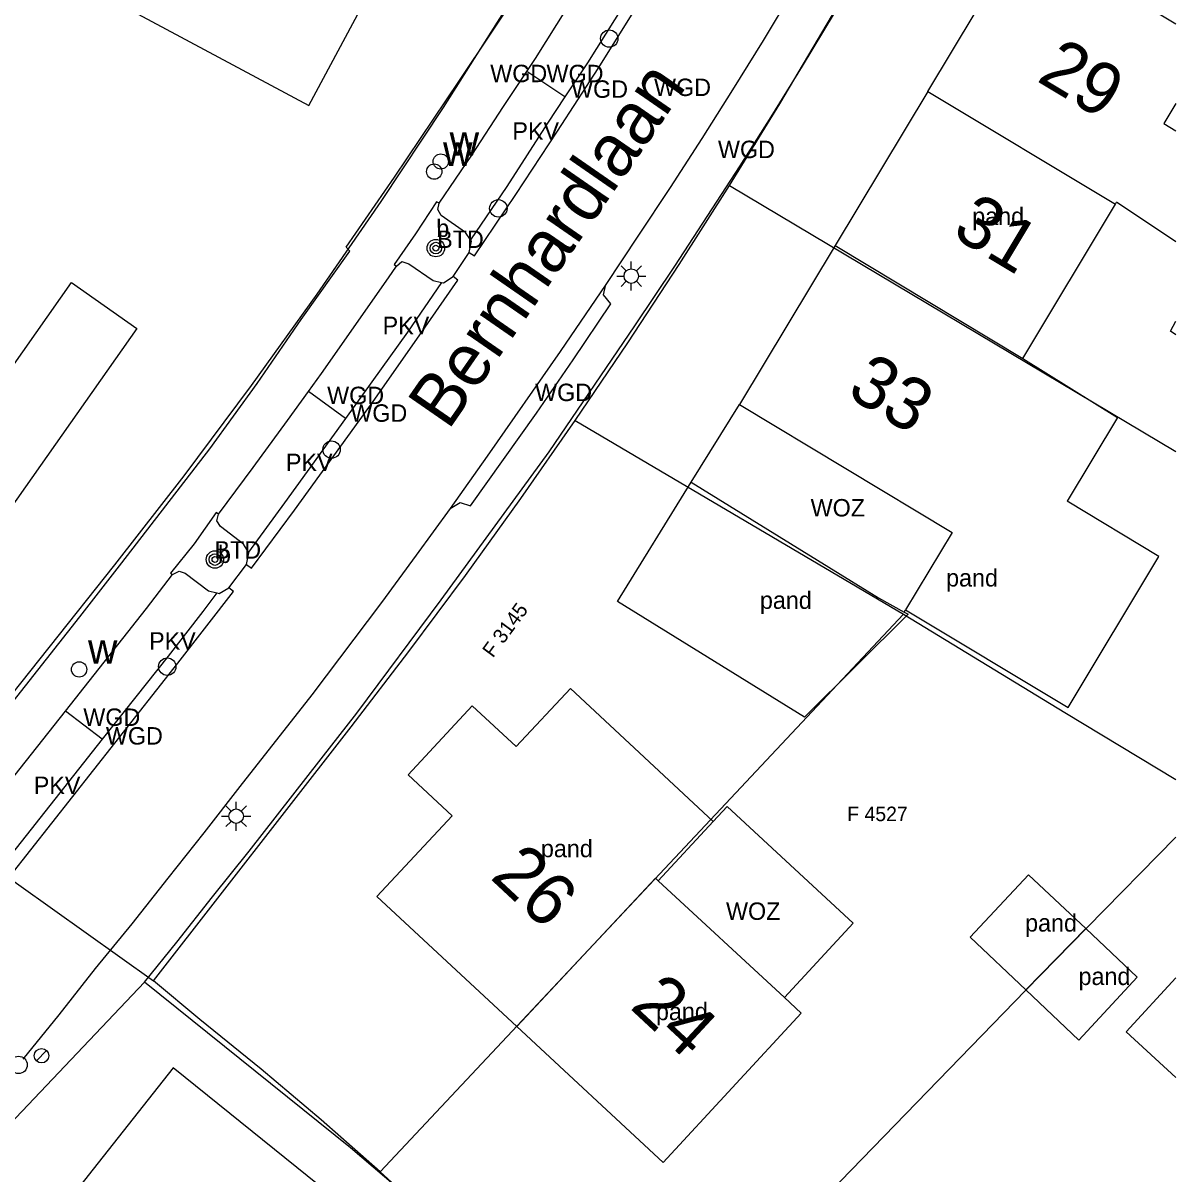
# Model space of a CAD drawing. Extents: x 198240 to 198429, y 356553 to 356721.
# Drawn here: x 198389.56 to 198429.25, y 356639.08 to 356678.7 of the extents above; entities that cross this region are included whole.
import ezdxf

# ---------------------------------------------------------------- set-up
doc = ezdxf.new("R2010")
doc.units = 0
for name, color, linetype in [('Afsluitpaal', 7, 'Continuous'), ('begroeid terreindeel kenmerkpunt', 7, 'Continuous'), ('bijgebouw', 7, 'Continuous'), ('BOOM', 7, 'Continuous'), ('grens individueel parkeervak', 7, 'Continuous'), ('Grens maaiveld', 7, 'Continuous'), ('grens WOZ object', 7, 'Continuous'), ('hoofdgebouw', 7, 'Continuous'), ('huisnummerreeks BGT', 7, 'Continuous'), ('identificerend kenmerkpunt bijpand', 7, 'Continuous'), ('identificerend kenmerkpunt pand', 7, 'Continuous'), ('identificerend kenmerkpunt parkeervak', 7, 'Continuous'), ('identificerend kenmerkpunt WOZ object', 7, 'Continuous'), ('kant verharding', 7, 'Continuous'), ('kolk', 7, 'Continuous'), ('LICHTMAST', 7, 'Continuous'), ('openbare ruimte label tekst', 7, 'Continuous'), ('Perceelnummer', 7, 'Continuous'), ('perceelsgrens_definitief', 7, 'Continuous'), ('tussenmuur', 7, 'Continuous'), ('tussenmuur bijgebouw (GBKN Zuid)', 7, 'Continuous'), ('vlakafsluiter', 7, 'Continuous'), ('waterleidingput', 7, 'Continuous'), ('wegdeel kenmerkpunt', 7, 'Continuous'), ('weginrichtingselement', 7, 'Continuous'), ('weginrichtingselement lijn', 7, 'Continuous')]:
    doc.layers.add(name, color=color, linetype=linetype)

msp = doc.modelspace()

# ---------------------------------------------------------------- linework, layer by layer
at = {"layer": 'Afsluitpaal'}
msp.add_line((198390.367, 356643.327), (198390.017, 356642.97), dxfattribs=at)
msp.add_circle((198390.194, 356643.147), 0.25, dxfattribs=at)
at = {"layer": 'bijgebouw'}
for p, q in [((198412.563, 356662.894), (198419.007, 356658.91)), ((198419.007, 356658.91), (198419.893, 356658.421))]:
    msp.add_line(p, q, dxfattribs=at)
for points in [[(198429.251, 356667.971), (198429.059, 356668.094), (198429.251, 356668.439)], [(198416.467, 356654.801), (198410.023, 356658.785), (198412.563, 356662.894)], [(198419.893, 356658.421), (198420.032, 356658.344), (198416.467, 356654.801)], [(198424.085, 356645.412), (198422.17, 356647.232), (198424.18, 356649.372), (198426.147, 356647.521)], [(198424.085, 356645.412), (198425.907, 356643.68), (198427.917, 356645.855), (198426.147, 356647.521)], [(198429.251, 356642.4), (198427.543, 356643.969), (198429.251, 356645.827)]]:
    msp.add_lwpolyline(points, dxfattribs=at)
at = {"layer": 'BOOM'}
for centre, radius in [((198403.77, 356670.952), 0.3), ((198403.77, 356670.952), 0.2), ((198403.77, 356670.952), 0.1), ((198396.164, 356660.23), 0.3), ((198396.164, 356660.23), 0.2), ((198396.164, 356660.23), 0.1)]:
    msp.add_circle(centre, radius, dxfattribs=at)
at = {"layer": 'grens individueel parkeervak'}
for p, q in [((198408.215, 356676.157), (198406.901, 356677.03)), ((198400.66, 356665.089), (198399.384, 356666.017)), ((198392.286, 356654.04), (198391.017, 356655.011))]:
    msp.add_line(p, q, dxfattribs=at)
at = {"layer": 'Grens maaiveld'}
for points in [[(198404.916, 356670.796), (198405.102, 356670.682), (198406.526, 356672.803), (198407.964, 356674.984), (198409.355, 356677.141), (198410.82, 356679.462), (198412.025, 356681.421), (198411.835, 356681.521)], [(198397.249, 356660.06), (198397.419, 356659.931), (198398.904, 356661.934), (198401.607, 356665.673), (198403.112, 356667.812), (198404.529, 356669.851), (198404.366, 356669.975)], [(198388.2, 356648.534), (198388.372, 356648.404), (198394.89, 356656.659), (198396.809, 356659.133), (198396.637, 356659.256)]]:
    msp.add_lwpolyline(points, dxfattribs=at)
at = {"layer": 'grens WOZ object'}
for p, q in [((198412.563, 356662.894), (198414.222, 356665.562)), ((198419.893, 356658.421), (198419.94, 356658.497)), ((198415.769, 356645.151), (198418.134, 356647.705))]:
    msp.add_line(p, q, dxfattribs=at)
msp.add_lwpolyline([(198413.323, 356651.216), (198413.795, 356651.724), (198418.134, 356647.705)], dxfattribs=at)
at = {"layer": 'hoofdgebouw'}
for p, q in [((198420.705, 356676.348), (198417.515, 356671.041)), ((198429.251, 356675.927), (198428.836, 356675.237)), ((198423.978, 356667.156), (198427.169, 356672.463)), ((198427.169, 356672.463), (198427.209, 356672.53)), ((198429.251, 356671.164), (198427.209, 356672.53)), ((198417.515, 356671.041), (198414.222, 356665.562)), ((198413.323, 356651.216), (198411.425, 356649.173)), ((198415.769, 356645.151), (198411.425, 356649.173))]:
    msp.add_line(p, q, dxfattribs=at)
for points in [[(198395.77, 356685.089), (198394.02, 356681.827), (198390.856, 356683.525), (198389.57, 356681.128), (198399.396, 356675.858), (198402.431, 356681.517)], [(198420.705, 356676.348), (198423.998, 356681.827), (198429.251, 356678.669)], [(198428.836, 356675.237), (198429.251, 356674.985)], [(198387.606, 356667.94), (198389.176, 356666.838), (198391.229, 356669.763), (198393.474, 356668.18), (198387.045, 356659.064), (198381.8, 356662.748)], [(198423.978, 356667.156), (198427.239, 356665.121), (198425.505, 356662.235)], [(198414.222, 356665.562), (198421.542, 356661.163), (198419.94, 356658.497)], [(198419.94, 356658.497), (198425.537, 356655.134), (198428.663, 356660.337), (198425.505, 356662.235)], [(198406.554, 356644.154), (198401.737, 356648.628), (198404.327, 356651.409), (198402.814, 356652.814), (198405.026, 356655.195), (198406.541, 356653.787), (198408.408, 356655.792), (198413.323, 356651.216)], [(198406.554, 356644.154), (198411.595, 356639.471), (198416.353, 356644.61), (198415.769, 356645.151)]]:
    msp.add_lwpolyline(points, dxfattribs=at)
at = {"layer": 'kant verharding'}
for p, q in [((198404.366, 356669.975), (198404.916, 356670.796)), ((198396.637, 356659.256), (198397.249, 356660.06)), ((198387.265, 356650.262), (198391.017, 356655.011)), ((198392.286, 356654.04), (198388.264, 356648.959))]:
    msp.add_line(p, q, dxfattribs=at)
for points in [[(198393.74, 356645.683), (198394.852, 356647.053), (198396.077, 356648.617), (198397.345, 356650.191), (198399.817, 356653.369), (198401.05, 356654.94), (198403.957, 356658.838), (198407.667, 356663.939), (198410.624, 356668.271), (198412.002, 356670.335), (198414.253, 356673.784), (198415.317, 356675.477), (198416.394, 356677.211), (198417.49, 356679.043), (198418.49, 356680.762), (198419.487, 356682.592), (198420.694, 356684.729), (198420.885, 356685.099)], [(198418.513, 356684.184), (198418.032, 356683.303), (198416.065, 356679.815), (198415.042, 356678.098), (198413.982, 356676.397), (198412.924, 356674.725), (198411.836, 356673.035), (198410.73, 356671.365), (198409.617, 356669.703)], [(198406.901, 356677.03), (198407.203, 356677.485), (198409.346, 356680.906), (198409.862, 356681.744)], [(198411.465, 356681.29), (198408.989, 356677.334), (198408.215, 356676.157)], [(198386.018, 356651.295), (198391.518, 356658.255), (198392.958, 356660.111), (198395.988, 356664.044), (198397.623, 356666.296), (198399.129, 356668.492), (198400.809, 356670.844), (198400.678, 356670.983), (198402.35, 356673.392), (198404.586, 356676.725), (198406.76, 356679.993)], [(198403.882, 356672.494), (198405.006, 356674.154), (198406.103, 356675.828), (198406.901, 356677.03)], [(198408.215, 356676.157), (198407.619, 356675.251), (198406.216, 356673.069), (198404.965, 356671.24)], [(198403.882, 356672.494), (198403.798, 356672.543), (198403.071, 356671.442), (198402.34, 356670.387), (198402.414, 356670.335)], [(198404.965, 356671.24), (198404.791, 356671.493), (198403.95, 356672.078), (198403.835, 356672.281), (198403.882, 356672.494)], [(198404.916, 356670.796), (198405.002, 356671.186), (198404.965, 356671.24)], [(198399.384, 356666.017), (198399.83, 356666.637), (198402.139, 356669.925), (198402.414, 356670.335)], [(198402.414, 356670.335), (198402.599, 356670.495), (198402.844, 356670.406), (198403.677, 356669.833), (198403.966, 356669.771)], [(198403.966, 356669.771), (198404.034, 356669.756), (198404.366, 356669.975)], [(198403.966, 356669.771), (198402.79, 356668.058), (198400.66, 356665.089)], [(198404.26, 356661.992), (198404.61, 356662.199), (198404.961, 356662.082), (198407.233, 356665.273), (198408.493, 356667.107), (198409.79, 356669.031), (198409.542, 356669.344), (198409.617, 356669.703)], [(198409.617, 356669.703), (198408.045, 356667.387), (198405.534, 356663.79), (198404.26, 356661.992)], [(198396.284, 356661.79), (198397.477, 356663.397), (198398.66, 356665.012), (198399.384, 356666.017)], [(198400.66, 356665.089), (198398.561, 356662.182), (198397.323, 356660.483)], [(198404.26, 356661.992), (198403.096, 356660.379), (198401.903, 356658.745), (198399.503, 356655.567), (198397.022, 356652.414), (198395.783, 356650.82), (198394.543, 356649.264), (198393.305, 356647.686), (198392.04, 356646.144), (198390.785, 356644.559), (198389.546, 356643.023)], [(198396.284, 356661.79), (198396.204, 356661.844), (198395.447, 356660.766), (198394.63, 356659.765), (198394.707, 356659.713)], [(198397.323, 356660.483), (198397.153, 356660.763), (198396.354, 356661.369), (198396.231, 356661.567), (198396.284, 356661.79)], [(198397.249, 356660.06), (198397.336, 356660.462), (198397.323, 356660.483)], [(198391.017, 356655.011), (198393.805, 356658.546), (198394.707, 356659.713)], [(198394.707, 356659.713), (198394.929, 356659.831), (198395.139, 356659.76), (198395.944, 356659.152), (198396.228, 356659.082)], [(198396.228, 356659.082), (198396.307, 356659.063), (198396.637, 356659.256)], [(198396.228, 356659.082), (198395.752, 356658.445), (198394.551, 356656.901), (198392.286, 356654.04)], [(198429.251, 356611.63), (198423.819, 356617.345), (198409.544, 356631.708), (198408.091, 356633.148), (198406.605, 356634.587), (198405.359, 356635.839), (198403.884, 356637.248), (198402.388, 356638.638), (198400.833, 356639.97), (198393.74, 356645.683)], [(198405.457, 356633.424), (198404.207, 356634.656), (198402.756, 356636.046), (198401.298, 356637.391), (198399.756, 356638.679), (198394.727, 356642.73), (198388.921, 356635.368)]]:
    msp.add_lwpolyline(points, dxfattribs=at)
at = {"layer": 'kolk'}
for centre in [(198409.74, 356678.166), (198405.923, 356672.32), (198400.179, 356664.016), (198394.523, 356656.542), (198389.403, 356642.831)]:
    msp.add_circle(centre, 0.3, dxfattribs=at)
at = {"layer": 'LICHTMAST'}
for p, q in [((198410.322, 356670.166), (198410.145, 356670.343)), ((198410.499, 356670.239), (198410.499, 356670.489)), ((198410.676, 356670.166), (198410.853, 356670.343)), ((198409.999, 356669.989), (198410.249, 356669.989)), ((198410.749, 356669.989), (198410.999, 356669.989)), ((198410.145, 356669.635), (198410.322, 356669.812)), ((198410.499, 356669.489), (198410.499, 356669.739)), ((198410.853, 356669.635), (198410.676, 356669.812)), ((198396.718, 356651.57), (198396.541, 356651.747)), ((198396.895, 356651.643), (198396.895, 356651.893)), ((198397.072, 356651.57), (198397.249, 356651.747)), ((198396.395, 356651.393), (198396.645, 356651.393)), ((198397.145, 356651.393), (198397.395, 356651.393)), ((198396.541, 356651.039), (198396.718, 356651.216)), ((198396.895, 356650.893), (198396.895, 356651.143)), ((198397.249, 356651.039), (198397.072, 356651.216))]:
    msp.add_line(p, q, dxfattribs=at)
for centre in [(198410.499, 356669.989), (198396.895, 356651.393)]:
    msp.add_circle(centre, 0.25, dxfattribs=at)
at = {"layer": 'perceelsgrens_definitief'}
for points in [[(198392.722, 356660.05), (198395.103, 356663.112), (198397.425, 356666.219), (198399.689, 356669.369), (198401.891, 356672.562), (198404.033, 356675.796), (198406.114, 356679.07), (198408.131, 356682.383), (198410.086, 356685.733), (198411.977, 356689.12), (198413.803, 356692.543), (198415.563, 356695.999), (198417.258, 356699.488), (198418.887, 356703.008), (198420.448, 356706.559), (198421.942, 356710.139)], [(198415.612, 356675.921), (198417.581, 356679.235), (198419.491, 356682.582), (198420.752, 356684.884)], [(198413.879, 356673.105), (198415.612, 356675.921)], [(198408.569, 356665.016), (198410.378, 356667.687), (198412.148, 356670.383), (198413.879, 356673.105)], [(198413.879, 356673.105), (198429.251, 356663.954)], [(198400.851, 356654.466), (198402.838, 356657.061), (198404.787, 356659.684), (198406.698, 356662.336), (198408.569, 356665.016)], [(198408.569, 356665.016), (198419.867, 356658.348)], [(198385.92, 356651.508), (198392.722, 356660.05)], [(198401.857, 356639.146), (198419.867, 356658.348)], [(198419.867, 356658.348), (198425.422, 356654.961), (198429.251, 356652.654)], [(198394.046, 356645.723), (198400.851, 356654.466)], [(198385.92, 356651.508), (198394.046, 356645.723)], [(198426.178, 356647.553), (198429.251, 356650.666)], [(198424.066, 356645.393), (198426.178, 356647.553)], [(198395.648, 356644.396), (198394.046, 356645.723)], [(198410.2, 356631.088), (198424.066, 356645.393)], [(198401.857, 356639.146), (198399.822, 356640.937), (198397.752, 356642.687), (198395.648, 356644.396)], [(198408.397, 356632.877), (198406.267, 356635.018), (198404.086, 356637.108), (198401.857, 356639.146)]]:
    msp.add_lwpolyline(points, dxfattribs=at)
at = {"layer": 'tussenmuur'}
for p, q in [((198420.705, 356676.348), (198427.169, 356672.463)), ((198417.515, 356671.041), (198423.978, 356667.156))]:
    msp.add_line(p, q, dxfattribs=at)
msp.add_lwpolyline([(198406.554, 356644.154), (198411.337, 356649.254), (198411.425, 356649.173)], dxfattribs=at)
at = {"layer": 'tussenmuur bijgebouw (GBKN Zuid)'}
msp.add_line((198424.085, 356645.412), (198426.147, 356647.521), dxfattribs=at)
at = {"layer": 'vlakafsluiter'}
msp.add_line((198387.884, 356639.508), (198393.74, 356645.683), dxfattribs=at)
at = {"layer": 'waterleidingput'}
for centre in [(198403.94, 356673.934), (198403.94, 356673.934), (198403.714, 356673.585), (198403.714, 356673.585), (198391.489, 356656.448), (198391.489, 356656.448)]:
    msp.add_circle(centre, 0.263, dxfattribs=at)
at = {"layer": 'weginrichtingselement lijn'}
for points in [[(198404.916, 356670.796), (198405.102, 356670.682), (198406.526, 356672.803), (198407.964, 356674.984), (198409.355, 356677.141), (198410.82, 356679.462), (198412.025, 356681.421), (198411.835, 356681.521)], [(198397.249, 356660.06), (198397.419, 356659.931), (198398.904, 356661.934), (198401.607, 356665.673), (198403.112, 356667.812), (198404.529, 356669.851), (198404.366, 356669.975)], [(198388.2, 356648.534), (198388.372, 356648.404), (198394.89, 356656.659), (198396.809, 356659.133), (198396.637, 356659.256)]]:
    msp.add_lwpolyline(points, dxfattribs=at)

# ---------------------------------------------------------------- texts
at = {"layer": 'begroeid terreindeel kenmerkpunt'}
for p in [(198403.815, 356670.956), (198396.149, 356660.26)]:
    msp.add_text('BTD', height=0.6, dxfattribs=at).set_placement(p)
at = {"layer": 'huisnummerreeks BGT'}
for s, rotation, p in [('29', 329, (198424.416, 356676.726)), ('31', 329, (198421.49, 356671.389)), ('33', 329, (198417.866, 356665.885)), ('26', 317.1, (198405.604, 356649.268)), ('24', 317.1, (198410.414, 356644.8))]:
    msp.add_text(s, height=1.8, rotation=rotation, dxfattribs=at).set_placement(p)
at = {"layer": 'identificerend kenmerkpunt bijpand'}
for p in [(198414.928, 356658.53), (198424.058, 356647.42), (198425.898, 356645.58)]:
    msp.add_text('pand', height=0.6, dxfattribs=at).set_placement(p)
at = {"layer": 'identificerend kenmerkpunt pand'}
for p in [(198422.238, 356671.75), (198421.338, 356659.3), (198407.388, 356649.98), (198411.348, 356644.37)]:
    msp.add_text('pand', height=0.6, dxfattribs=at).set_placement(p)
at = {"layer": 'identificerend kenmerkpunt parkeervak'}
for p in [(198406.406, 356674.683), (198401.937, 356667.989), (198398.608, 356663.274), (198393.898, 356657.129), (198389.928, 356652.157)]:
    msp.add_text('PKV', height=0.6, dxfattribs=at).set_placement(p)
at = {"layer": 'identificerend kenmerkpunt WOZ object'}
for p in [(198416.674, 356661.712), (198413.761, 356647.823)]:
    msp.add_text('WOZ', height=0.6, dxfattribs=at).set_placement(p)
at = {"layer": 'openbare ruimte label tekst'}
msp.add_text('Bernhardlaan', height=1.8, rotation=55.3, dxfattribs=at).set_placement((198404.195, 356664.648))
at = {"layer": 'Perceelnummer'}
msp.add_text('F 3145', height=0.5, rotation=53.6, dxfattribs=at).set_placement((198405.735, 356656.82))
msp.add_text('F 4527', height=0.5, dxfattribs=at).set_placement((198417.934, 356651.222))
at = {"layer": 'waterleidingput'}
for p in [(198404.244, 356674.132), (198404.018, 356673.783), (198391.793, 356656.646)]:
    msp.add_text('w', height=1.05, dxfattribs=at).set_placement(p)
at = {"layer": 'wegdeel kenmerkpunt'}
for p in [(198405.643, 356676.665), (198407.581, 356676.663), (198408.426, 356676.127), (198411.283, 356676.188), (198413.483, 356674.05), (198400.028, 356665.58), (198407.188, 356665.685), (198400.825, 356664.973), (198391.633, 356654.501), (198392.41, 356653.859)]:
    msp.add_text('WGD', height=0.6, dxfattribs=at).set_placement(p)
at = {"layer": 'weginrichtingselement'}
for p in [(198403.786, 356671.337), (198396.271, 356660.11)]:
    msp.add_text('b', height=0.6, rotation=0.2905, dxfattribs=at).set_placement(p)

doc.saveas('drawing.dxf')
